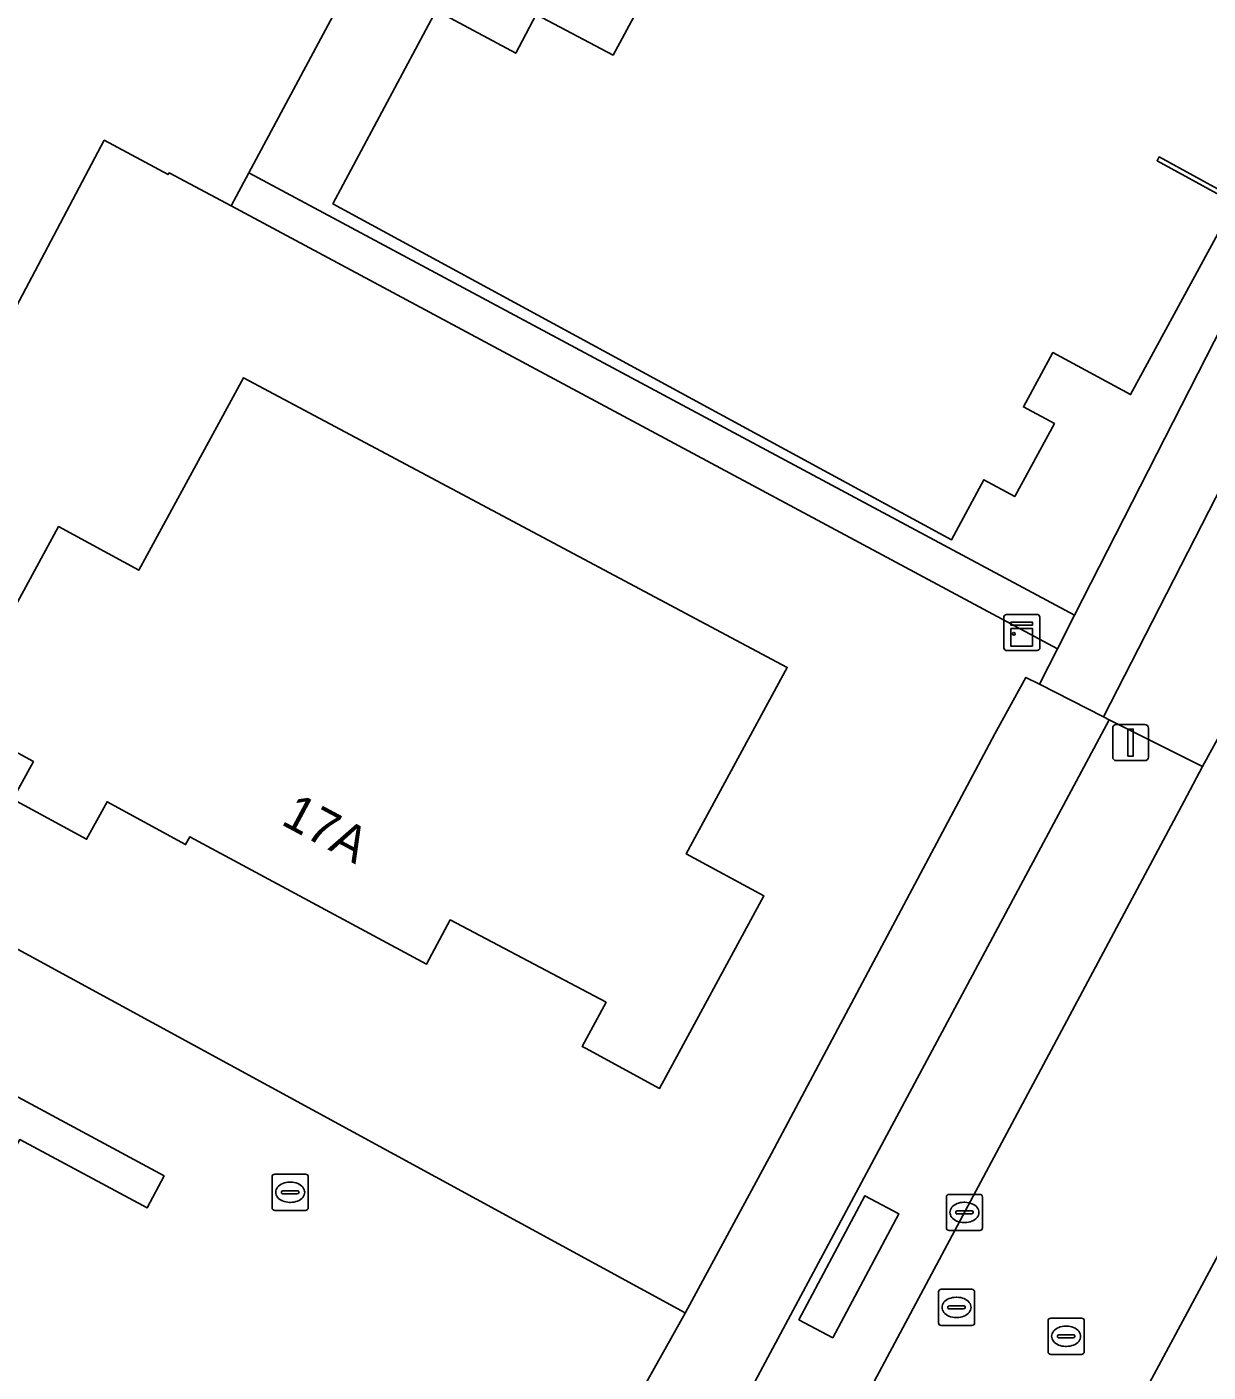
# Model space of a CAD drawing. Extents: x 159489 to 160304, y 383825 to 384531.
# Drawn here: x 159891.43 to 159924.09, y 384218.65 to 384255.84 of the extents above; entities that cross this region are included whole.
import ezdxf

# ---------------------------------------------------------------- set-up
doc = ezdxf.new("R2010")
doc.units = 0
for name, color, linetype in [('IMGEO_Groenvoorziening', 7, 'Continuous'), ('IMGEO_Kast', 7, 'Continuous'), ('IMGEO_Kolk', 7, 'Continuous'), ('IMGEO_Lichtmast', 7, 'Continuous'), ('IMGEO_OVBaan_gesloten', 7, 'Continuous'), ('IMGEO_Pand', 7, 'Continuous'), ('IMGEO_Pand_nummerreeks', 7, 'Continuous'), ('IMGEO_Rioolput', 7, 'Continuous'), ('IMGEO_Voetpad_gesloten', 7, 'Continuous'), ('IMGEO_Voetpad_open', 7, 'Continuous')]:
    doc.layers.add(name, color=color, linetype=linetype)

msp = doc.modelspace()

# ---------------------------------------------------------------- linework, layer by layer
at = {"layer": 'IMGEO_Groenvoorziening'}
msp.add_lwpolyline([(159889.617, 384305.204), (159860.893, 384252.084), (159885.992, 384238.575), (159887.317, 384240.977), (159890.428, 384246.794), (159893.567, 384252.708), (159895.332, 384251.761), (159895.356, 384251.808), (159897.071, 384250.898), (159897.211, 384251.158), (159897.56, 384251.811), (159903.247, 384262.426), (159905.005, 384261.493), (159908.783, 384268.547), (159910.489, 384267.64), (159910.985, 384268.553), (159916.649, 384278.985), (159918.393, 384278.059), (159923.105, 384286.939), (159920.237, 384290.402), (159911.305, 384301.186)], dxfattribs=at)
for points in [[(159921.354, 384236.689), (159923.939, 384235.4), (159925.093, 384237.495), (159925.839, 384239.117), (159927.163, 384242.784), (159924.884, 384243.966), (159921.198, 384236.767)], [(159895.218, 384224.077), (159884.638, 384229.776), (159884.159, 384228.887), (159885.923, 384227.942), (159885.464, 384227.051), (159890.749, 384224.221), (159891.233, 384225.088), (159894.754, 384223.196)]]:
    msp.add_lwpolyline(points, close=True, dxfattribs=at)
at = {"layer": 'IMGEO_Kast'}
for p, q in [((159918.516, 384239.6), (159919.357, 384239.6)), ((159919.357, 384239.6), (159918.516, 384239.6)), ((159918.441, 384238.675), (159918.441, 384239.516)), ((159918.441, 384239.516), (159918.441, 384238.675)), ((159919.441, 384239.525), (159919.441, 384238.684)), ((159919.441, 384238.684), (159919.441, 384239.525)), ((159919.366, 384238.6), (159918.525, 384238.6)), ((159918.525, 384238.6), (159919.366, 384238.6))]:
    msp.add_line(p, q, dxfattribs=at)
for points in [[(159918.636, 384239.39), (159919.236, 384239.39), (159919.236, 384239.305), (159918.636, 384239.305), (159918.636, 384239.39)], [(159918.636, 384239.215), (159919.236, 384239.215), (159919.236, 384238.726), (159918.636, 384238.726), (159918.636, 384239.215)]]:
    msp.add_lwpolyline(points, dxfattribs=at)
msp.add_circle((159918.72, 384239.064), 0.0377, dxfattribs=at)
for centre, start, end in [((159918.519, 384239.522), 92.4484, 184.2845), ((159918.519, 384239.522), 92.4484, 184.2845), ((159919.363, 384239.522), 2.4484, 94.2845), ((159919.363, 384239.522), 2.4484, 94.2845), ((159918.519, 384238.678), 182.4484, 274.2845), ((159918.519, 384238.678), 182.4484, 274.2845), ((159919.363, 384238.678), 272.4484, 4.2845), ((159919.363, 384238.678), 272.4484, 4.2845)]:
    msp.add_arc(centre, 0.0779, start, end, dxfattribs=at)
at = {"layer": 'IMGEO_Kolk'}
for p, q in [((159898.206, 384223.199), (159898.206, 384224.051)), ((159898.281, 384224.125), (159899.133, 384224.125)), ((159899.207, 384224.051), (159899.207, 384223.199)), ((159898.465, 384223.619), (159898.465, 384223.631)), ((159898.508, 384223.668), (159898.906, 384223.668)), ((159898.694, 384223.905), (159898.719, 384223.905)), ((159898.949, 384223.631), (159898.949, 384223.619)), ((159898.903, 384223.582), (159898.505, 384223.582)), ((159898.717, 384223.345), (159898.692, 384223.345)), ((159916.854, 384222.641), (159916.854, 384223.493)), ((159916.929, 384223.567), (159917.781, 384223.567)), ((159917.342, 384223.347), (159917.367, 384223.347)), ((159917.855, 384223.493), (159917.855, 384222.641)), ((159899.133, 384223.125), (159898.281, 384223.125)), ((159917.113, 384223.061), (159917.113, 384223.073)), ((159917.551, 384223.024), (159917.153, 384223.024)), ((159917.156, 384223.11), (159917.554, 384223.11)), ((159917.597, 384223.073), (159917.597, 384223.061)), ((159917.781, 384222.567), (159916.929, 384222.567)), ((159917.365, 384222.787), (159917.34, 384222.787))]:
    msp.add_line(p, q, dxfattribs=at)
for points in [[(159898.206, 384223.199), (159898.206, 384224.051)], [(159898.281, 384224.125), (159899.133, 384224.125)], [(159899.207, 384224.051), (159899.207, 384223.199)], [(159916.854, 384222.641), (159916.854, 384223.493)], [(159916.929, 384223.567), (159917.781, 384223.567)], [(159917.855, 384223.493), (159917.855, 384222.641)], [(159899.133, 384223.125), (159898.281, 384223.125)], [(159917.781, 384222.567), (159916.929, 384222.567)]]:
    msp.add_lwpolyline(points, dxfattribs=at)
for centre, radius, start, end in [((159898.283, 384224.049), 0.0765, 91.552, 178.448), ((159898.283, 384224.049), 0.0765, 91.552, 178.448), ((159899.131, 384224.049), 0.0765, 1.552, 88.448), ((159899.131, 384224.049), 0.0765, 1.552, 88.448), ((159898.505, 384223.628), 0.0403, 85.8775, 175.7526), ((159898.502, 384223.618), 0.0366, 178.938, 274.7102), ((159898.906, 384223.625), 0.043, 264.8664, 352.4533), ((159898.91, 384223.63), 0.0386, 1.7309, 96.639), ((159916.931, 384223.491), 0.0765, 91.552, 178.448), ((159916.931, 384223.491), 0.0765, 91.552, 178.448), ((159917.779, 384223.491), 0.0765, 1.552, 88.448), ((159917.779, 384223.491), 0.0765, 1.552, 88.448), ((159898.283, 384223.201), 0.0765, 181.552, 268.448), ((159898.283, 384223.201), 0.0765, 181.552, 268.448), ((159899.131, 384223.201), 0.0765, 271.552, 358.448), ((159899.131, 384223.201), 0.0765, 271.552, 358.448), ((159917.153, 384223.07), 0.0403, 85.8775, 175.7526), ((159917.15, 384223.06), 0.0366, 178.938, 274.7102), ((159917.554, 384223.067), 0.043, 264.8664, 352.4533), ((159917.558, 384223.072), 0.0386, 1.7309, 96.639), ((159916.931, 384222.643), 0.0765, 181.552, 268.448), ((159916.931, 384222.643), 0.0765, 181.552, 268.448), ((159917.779, 384222.643), 0.0765, 271.552, 358.448), ((159917.779, 384222.643), 0.0765, 271.552, 358.448)]:
    msp.add_arc(centre, radius, start, end, dxfattribs=at)
for centre, major_axis, ratio, start_param, end_param in [((159898.693, 384223.625), (-0.387, 0.002), 0.722429, 4.712389, 7.853982), ((159898.718, 384223.625), (-0.39, 0.002), 0.717154, 1.570796, 4.712389), ((159917.341, 384223.067), (-0.387, 0.002), 0.722429, 4.712389, 7.853982), ((159917.366, 384223.067), (-0.39, 0.002), 0.717154, 1.570796, 4.712389)]:
    msp.add_ellipse(centre, major_axis=major_axis, ratio=ratio, start_param=start_param, end_param=end_param, dxfattribs=at)
at = {"layer": 'IMGEO_Lichtmast'}
for p, q in [((159921.455, 384235.657), (159921.455, 384236.457)), ((159921.455, 384236.457), (159921.455, 384235.657)), ((159921.555, 384236.557), (159922.345, 384236.557)), ((159922.345, 384236.557), (159921.555, 384236.557)), ((159922.445, 384236.457), (159922.445, 384235.657)), ((159922.445, 384235.657), (159922.445, 384236.457)), ((159922.345, 384235.557), (159921.555, 384235.557)), ((159921.555, 384235.557), (159922.345, 384235.557))]:
    msp.add_line(p, q, dxfattribs=at)
msp.add_lwpolyline([(159921.875, 384236.432), (159922.025, 384236.432), (159922.025, 384235.682), (159921.875, 384235.682), (159921.875, 384236.432)], dxfattribs=at)
for centre, start, end in [((159921.555, 384236.457), 90, 180), ((159921.555, 384236.457), 90, 180), ((159922.345, 384236.457), 0, 90), ((159922.345, 384236.457), 360, 90), ((159921.555, 384235.657), 180, 270), ((159921.555, 384235.657), 180, 270), ((159922.345, 384235.657), 270, 0), ((159922.345, 384235.657), 270, 0)]:
    msp.add_arc(centre, 0.1, start, end, dxfattribs=at)
at = {"layer": 'IMGEO_OVBaan_gesloten'}
msp.add_lwpolyline([(159889.629, 384157.595), (159891.699, 384161.454), (159894.341, 384166.312), (159894.932, 384167.392), (159899.663, 384176.232), (159917.37, 384209.066), (159917.564, 384209.236), (159933.717, 384239.272), (159933.611, 384239.33), (159934.188, 384240.289), (159934.691, 384241.032), (159927.855, 384244.699), (159927.163, 384242.784), (159925.839, 384239.117), (159925.093, 384237.495), (159923.939, 384235.4), (159923.428, 384234.441), (159911.615, 384212.316), (159911.69, 384212.238), (159911.593, 384212.02), (159910.296, 384209.51), (159906.952, 384203.585), (159893.253, 384178.177), (159888.635, 384169.463)], dxfattribs=at)
at = {"layer": 'IMGEO_Pand'}
for points in [[(159927.842, 384255.225), (159925.054, 384256.682), (159925.394, 384257.333), (159916.845, 384261.96), (159916.807, 384261.889), (159914.874, 384258.225), (159914.118, 384256.793), (159909.845, 384259.151), (159907.639, 384255.062), (159905.508, 384256.185), (159904.944, 384255.114), (159902.743, 384256.292), (159899.889, 384250.952), (159916.992, 384241.661), (159917.894, 384243.324), (159918.748, 384242.86), (159919.842, 384244.875), (159918.987, 384245.338), (159919.802, 384246.839), (159921.947, 384245.676), (159924.82, 384250.97), (159922.682, 384252.143), (159922.738, 384252.249), (159925.496, 384250.736)], [(159912.455, 384238.136), (159897.417, 384246.144), (159894.517, 384240.823), (159892.302, 384242.03), (159889.412, 384236.726), (159891.604, 384235.532), (159891.04, 384234.496), (159893.077, 384233.385), (159893.641, 384234.422), (159895.816, 384233.236), (159895.931, 384233.447), (159902.477, 384229.929), (159903.135, 384231.154), (159907.444, 384228.878), (159906.782, 384227.656), (159906.871, 384227.608), (159908.923, 384226.496), (159911.807, 384231.817), (159909.661, 384232.979)]]:
    msp.add_lwpolyline(points, close=True, dxfattribs=at)
at = {"layer": 'IMGEO_Rioolput'}
for p, q in [((159916.635, 384220.016), (159916.635, 384220.868)), ((159916.71, 384220.942), (159917.562, 384220.942)), ((159917.123, 384220.722), (159917.148, 384220.722)), ((159917.636, 384220.868), (159917.636, 384220.016)), ((159916.894, 384220.436), (159916.894, 384220.448)), ((159917.332, 384220.399), (159916.934, 384220.399)), ((159916.937, 384220.485), (159917.335, 384220.485)), ((159917.378, 384220.448), (159917.378, 384220.436)), ((159917.562, 384219.942), (159916.71, 384219.942)), ((159917.146, 384220.162), (159917.121, 384220.162)), ((159919.666, 384219.217), (159919.666, 384220.069)), ((159919.741, 384220.143), (159920.593, 384220.143)), ((159920.154, 384219.923), (159920.179, 384219.923)), ((159920.667, 384220.069), (159920.667, 384219.217)), ((159919.925, 384219.637), (159919.925, 384219.649)), ((159920.363, 384219.6), (159919.965, 384219.6)), ((159919.968, 384219.686), (159920.366, 384219.686)), ((159920.409, 384219.649), (159920.409, 384219.637)), ((159920.593, 384219.143), (159919.741, 384219.143)), ((159920.177, 384219.363), (159920.152, 384219.363))]:
    msp.add_line(p, q, dxfattribs=at)
for points in [[(159916.635, 384220.016), (159916.635, 384220.868)], [(159916.71, 384220.942), (159917.562, 384220.942)], [(159917.636, 384220.868), (159917.636, 384220.016)], [(159917.562, 384219.942), (159916.71, 384219.942)], [(159919.666, 384219.217), (159919.666, 384220.069)], [(159919.741, 384220.143), (159920.593, 384220.143)], [(159920.667, 384220.069), (159920.667, 384219.217)], [(159920.593, 384219.143), (159919.741, 384219.143)]]:
    msp.add_lwpolyline(points, dxfattribs=at)
for centre, radius, start, end in [((159916.712, 384220.866), 0.0765, 91.552, 178.448), ((159916.712, 384220.866), 0.0765, 91.552, 178.448), ((159917.56, 384220.866), 0.0765, 1.552, 88.448), ((159917.56, 384220.866), 0.0765, 1.552, 88.448), ((159916.934, 384220.445), 0.0403, 85.8775, 175.7526), ((159916.931, 384220.435), 0.0366, 178.938, 274.7102), ((159917.335, 384220.442), 0.043, 264.8664, 352.4533), ((159917.339, 384220.447), 0.0386, 1.7309, 96.639), ((159916.712, 384220.018), 0.0765, 181.552, 268.448), ((159916.712, 384220.018), 0.0765, 181.552, 268.448), ((159917.56, 384220.018), 0.0765, 271.552, 358.448), ((159917.56, 384220.018), 0.0765, 271.552, 358.448), ((159919.743, 384220.067), 0.0765, 91.552, 178.448), ((159919.743, 384220.067), 0.0765, 91.552, 178.448), ((159920.591, 384220.067), 0.0765, 1.552, 88.448), ((159920.591, 384220.067), 0.0765, 1.552, 88.448), ((159919.965, 384219.646), 0.0403, 85.8775, 175.7526), ((159919.962, 384219.636), 0.0366, 178.938, 274.7102), ((159920.366, 384219.643), 0.043, 264.8664, 352.4533), ((159920.37, 384219.648), 0.0386, 1.7309, 96.639), ((159919.743, 384219.219), 0.0765, 181.552, 268.448), ((159919.743, 384219.219), 0.0765, 181.552, 268.448), ((159920.591, 384219.219), 0.0765, 271.552, 358.448), ((159920.591, 384219.219), 0.0765, 271.552, 358.448)]:
    msp.add_arc(centre, radius, start, end, dxfattribs=at)
for centre, major_axis, ratio, start_param, end_param in [((159917.122, 384220.442), (-0.387, 0.002), 0.722429, 4.712389, 7.853982), ((159917.147, 384220.442), (-0.39, 0.002), 0.717154, 1.570796, 4.712389), ((159920.153, 384219.643), (-0.387, 0.002), 0.722429, 4.712389, 7.853982), ((159920.178, 384219.643), (-0.39, 0.002), 0.717154, 1.570796, 4.712389)]:
    msp.add_ellipse(centre, major_axis=major_axis, ratio=ratio, start_param=start_param, end_param=end_param, dxfattribs=at)
at = {"layer": 'IMGEO_Voetpad_gesloten'}
for points in [[(159910.489, 384267.64), (159908.783, 384268.547), (159905.005, 384261.493), (159903.247, 384262.426), (159897.56, 384251.811), (159920.399, 384239.576), (159929.496, 384257.407)], [(159907.639, 384255.062), (159909.845, 384259.151), (159914.118, 384256.793), (159914.874, 384258.225), (159916.807, 384261.889), (159916.845, 384261.96), (159925.394, 384257.333), (159925.054, 384256.682), (159927.842, 384255.225), (159925.496, 384250.736), (159922.738, 384252.249), (159922.682, 384252.143), (159924.82, 384250.97), (159921.947, 384245.676), (159919.802, 384246.839), (159918.987, 384245.338), (159919.842, 384244.875), (159918.748, 384242.86), (159917.894, 384243.324), (159916.992, 384241.661), (159899.889, 384250.952), (159902.743, 384256.292), (159904.944, 384255.114), (159905.508, 384256.185)], [(159918.191, 384236.296), (159919.056, 384237.859), (159919.426, 384237.669), (159919.928, 384238.653), (159897.071, 384250.898), (159895.356, 384251.808), (159895.332, 384251.761), (159893.567, 384252.708), (159890.428, 384246.794), (159887.317, 384240.977), (159885.992, 384238.575), (159860.893, 384252.084), (159858.696, 384248.021), (159909.525, 384220.345), (159909.594, 384220.307), (159909.635, 384220.285), (159912.017, 384224.696)], [(159909.661, 384232.979), (159911.807, 384231.817), (159908.923, 384226.496), (159906.871, 384227.608), (159906.782, 384227.656), (159907.444, 384228.878), (159903.135, 384231.154), (159902.477, 384229.929), (159895.931, 384233.447), (159895.816, 384233.236), (159893.641, 384234.422), (159893.077, 384233.385), (159891.04, 384234.496), (159891.604, 384235.532), (159889.412, 384236.726), (159892.302, 384242.03), (159894.517, 384240.823), (159897.417, 384246.144), (159912.455, 384238.136)]]:
    msp.add_lwpolyline(points, close=True, dxfattribs=at)
at = {"layer": 'IMGEO_Voetpad_open'}
for points in [[(159944.409, 384267.482), (159943.097, 384269.065), (159931.694, 384261.188), (159930.066, 384258.181), (159929.922, 384258.242), (159929.496, 384257.407), (159920.399, 384239.576), (159919.928, 384238.653), (159919.426, 384237.669), (159921.198, 384236.767), (159924.884, 384243.966), (159927.163, 384242.784), (159927.855, 384244.699), (159925.781, 384245.753), (159932.853, 384259.535)], [(159897.56, 384251.811), (159897.211, 384251.158), (159897.071, 384250.898), (159919.928, 384238.653), (159920.399, 384239.576)], [(159936.314, 384237.873), (159937.261, 384239.696), (159934.691, 384241.032), (159934.188, 384240.289), (159933.611, 384239.33), (159933.717, 384239.272), (159917.564, 384209.236), (159920.172, 384207.756), (159922.992, 384213.07)], [(159911.593, 384212.02), (159911.69, 384212.238), (159911.615, 384212.316), (159909.028, 384213.664), (159911.916, 384219.059), (159921.354, 384236.689), (159921.198, 384236.767), (159919.426, 384237.669), (159919.056, 384237.859), (159918.191, 384236.296), (159912.017, 384224.696), (159909.635, 384220.285), (159904.01, 384210.25), (159903.822, 384209.904), (159904.02, 384209.797), (159906.135, 384208.661), (159906.255, 384208.597), (159891.472, 384180.7), (159893.253, 384178.177), (159906.952, 384203.585), (159910.296, 384209.51)], [(159923.428, 384234.441), (159923.939, 384235.4), (159921.354, 384236.689), (159911.916, 384219.059), (159909.028, 384213.664), (159911.615, 384212.316)], [(159884.159, 384228.887), (159884.638, 384229.776), (159895.218, 384224.077), (159894.754, 384223.196), (159891.233, 384225.088), (159890.749, 384224.221), (159885.464, 384227.051), (159885.923, 384227.942)], [(159915.539, 384223.03), (159914.602, 384223.529), (159912.778, 384220.1), (159913.714, 384219.602)], [(159913.714, 384219.602), (159912.778, 384220.1), (159914.602, 384223.529), (159915.539, 384223.03)]]:
    msp.add_lwpolyline(points, close=True, dxfattribs=at)
msp.add_lwpolyline([(159891.133, 384216.725), (159896.603, 384213.786), (159896.79, 384214.13), (159897.66, 384213.669), (159897.474, 384213.317), (159902.944, 384210.377), (159903.13, 384210.719), (159904.01, 384210.25), (159909.635, 384220.285), (159909.594, 384220.307), (159909.525, 384220.345), (159858.696, 384248.021)], dxfattribs=at)

# ---------------------------------------------------------------- texts
at = {"layer": 'IMGEO_Pand_nummerreeks'}
msp.add_text('17A', height=1, rotation=331.7417, dxfattribs=at).set_placement((159898.42, 384233.813))

doc.saveas('drawing.dxf')
